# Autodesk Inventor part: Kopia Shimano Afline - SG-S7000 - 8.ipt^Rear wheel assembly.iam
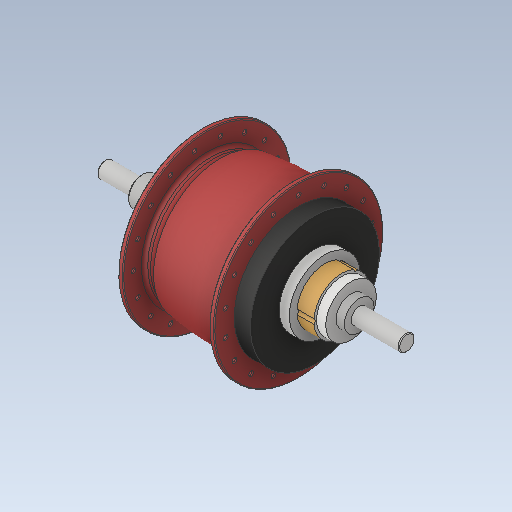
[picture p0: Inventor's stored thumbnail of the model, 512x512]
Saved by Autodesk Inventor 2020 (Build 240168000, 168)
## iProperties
Created: 2017-09
Part Number: Kopia Shimano Afline - SG-S7000 - 8.ipt^Rear wheel assembly.iam
Material: Ogólny
Document SubType Name: Modeling
Designer: Tomasz
Density: 1 g/cm^3
Appearance: Domyślna
Sending System: SolidWorks 2017
Last Author: Tomasz
Last Saved: 2017-09-11
Author: Tomasz
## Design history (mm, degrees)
feature "Shimano Afline - SG-S7000 - 8.ipt"
node "Bryła1"
